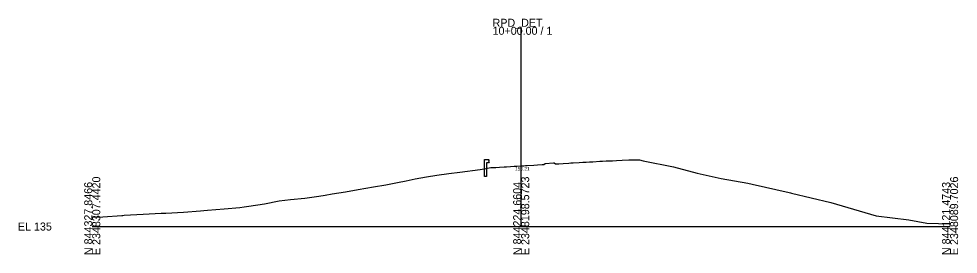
# Model space of a CAD drawing. Extents: x -26 to 2348503, y -10 to 844218.
# Drawn here: x -25.7 to 302.8, y -9.7 to 72.7 of the extents above; entities that cross this region are included whole.
import ezdxf

# ---------------------------------------------------------------- set-up
doc = ezdxf.new("R2010")
doc.units = 0
for name, color, linetype in [('Default', 7, 'Continuous'), ('Exist Cross Section Cell', 7, 'Continuous'), ('Exist XS Center Line Elevation Label', 7, 'Continuous'), ('Exist XS Ground Line', 7, 'Continuous'), ('Prop CMT Guardrail Widen Shoulder', 7, 'Continuous')]:
    doc.layers.add(name, color=color, linetype=linetype)

msp = doc.modelspace()

# ---------------------------------------------------------------- linework, layer by layer
at = {"layer": 'Exist Cross Section Cell'}
for p, q in [((150, 0), (150, 69.89)), ((0, 0), (150, 0)), ((150, 0), (300, 0))]:
    msp.add_line(p, q, dxfattribs=at)
at = {"layer": 'Exist XS Ground Line'}
msp.add_lwpolyline([(0, 3.23), (3.66, 3.37), (10.3, 3.86), (10.73, 3.89), (11.18, 3.92), (17.8, 4.3), (24.08, 4.64), (24.88, 4.68), (25.72, 4.72), (31.95, 5.07), (37.86, 5.5), (39.03, 5.6), (40.26, 5.7), (46.1, 6.17), (51.64, 6.68), (53.17, 6.86), (54.79, 7.09), (60.25, 7.91), (65.42, 8.95), (67.32, 9.27), (69.33, 9.49), (74.39, 9.97), (79.19, 10.65), (81.47, 11.02), (83.87, 11.38), (88.54, 12.11), (92.97, 12.92), (95.62, 13.41), (98.41, 13.91), (102.69, 14.64), (106.75, 15.45), (109.76, 16.03), (112.94, 16.64), (116.84, 17.37), (120.53, 17.94), (124.67, 18.58), (128.52, 19.06), (135.71, 19.99), (137.07, 20.2), (139.43, 20.61), (141.16, 20.69), (142.39, 20.78), (144.06, 20.85), (144.44, 20.87), (144.85, 20.89), (146.23, 20.97), (147.51, 21.06), (148.5, 21.12), (150, 21.21), (150.93, 21.27), (151.52, 21.3), (152.15, 21.33), (154.38, 21.46), (155.73, 21.55), (157.33, 21.65), (157.98, 21.73), (158.37, 22.09), (161.25, 22.25), (161.56, 22.27), (161.98, 21.91), (162.29, 21.94), (163.21, 21.98), (164.66, 22.05), (166.61, 22.18), (167.4, 22.23), (168.15, 22.28), (170.29, 22.41), (171.6, 22.48), (172.73, 22.54), (173.91, 22.61), (175.03, 22.67), (177.56, 22.82), (178, 22.84), (178.43, 22.86), (179.78, 22.93), (181.16, 23), (181.93, 23.04), (183.31, 23.1), (185.27, 23.2), (187.6, 23.3), (187.95, 23.3), (191.33, 23.29), (192.61, 22.97), (203.31, 20.91), (211.56, 18.69), (219.95, 16.77), (229.24, 15.16), (230.76, 14.83), (243.78, 11.88), (244.17, 11.8), (244.53, 11.71), (258.32, 8.36), (274.15, 3.79), (285.59, 2.33), (291.92, 1.12), (300, 0.97)], dxfattribs=at)
at = {"layer": 'Prop CMT Guardrail Widen Shoulder'}
for p, q in [((137.19, 17.49), (137.19, 23.49)), ((137.19, 23.49), (138.52, 23.49)), ((138.52, 23.49), (138.79, 23.2)), ((138.79, 23.2), (138.52, 22.91)), ((138.52, 22.33), (137.86, 22.33)), ((137.86, 22.33), (137.86, 17.49)), ((138.52, 22.91), (138.79, 22.62)), ((138.79, 22.62), (138.52, 22.33)), ((137.86, 17.49), (137.19, 17.49))]:
    msp.add_line(p, q, dxfattribs=at)

# ---------------------------------------------------------------- texts
at = {"layer": 'Default'}
msp.add_text('-', height=0.0001, dxfattribs=at).set_placement((0, 0))
at = {"layer": 'Exist Cross Section Cell'}
for s, p in [('RPD_DET', (140, 69.89)), ('10+00.00 / 1', (140, 67.09)), ('EL 135', (-26, -1.4))]:
    msp.add_text(s, height=2.8, dxfattribs=at).set_placement(p)
for s, p in [('E 2348307.4420', (2.8, -10)), ('E 2348198.5723', (152.8, -10)), ('E 2348089.7026', (302.8, -10)), ('N 844327.8466', (0, -10)), ('N 844224.6604', (150, -10)), ('N 844121.4743', (300, -10))]:
    msp.add_text(s, height=2.8, rotation=90, dxfattribs=at).set_placement(p)
at = {"layer": 'Exist XS Center Line Elevation Label'}
msp.add_text('156.21', height=1.2, dxfattribs=at).set_placement((147.86, 19.61))

doc.saveas('drawing.dxf')
